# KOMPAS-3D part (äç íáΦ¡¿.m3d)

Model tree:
1. Эскиз:1
2. Операция выдавливания:1
     Расстояние 1 = 2; Расстояние 2 = 4
3. Эскиз:2
4. Операция выдавливания:2
     Расстояние 1 = 0.6; Расстояние 2 = 4
5. Эскиз:3
6. Операция выдавливания:3
     Расстояние 1 = 0.6; Расстояние 2 = 4
7. Скругление:1
     Радиус = 0.3
8. Скругление:2
     Радиус = 0.1
9. Скругление:3
     Радиус = 0.1

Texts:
  Сплав АЛ8  ГОСТ 1583-93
